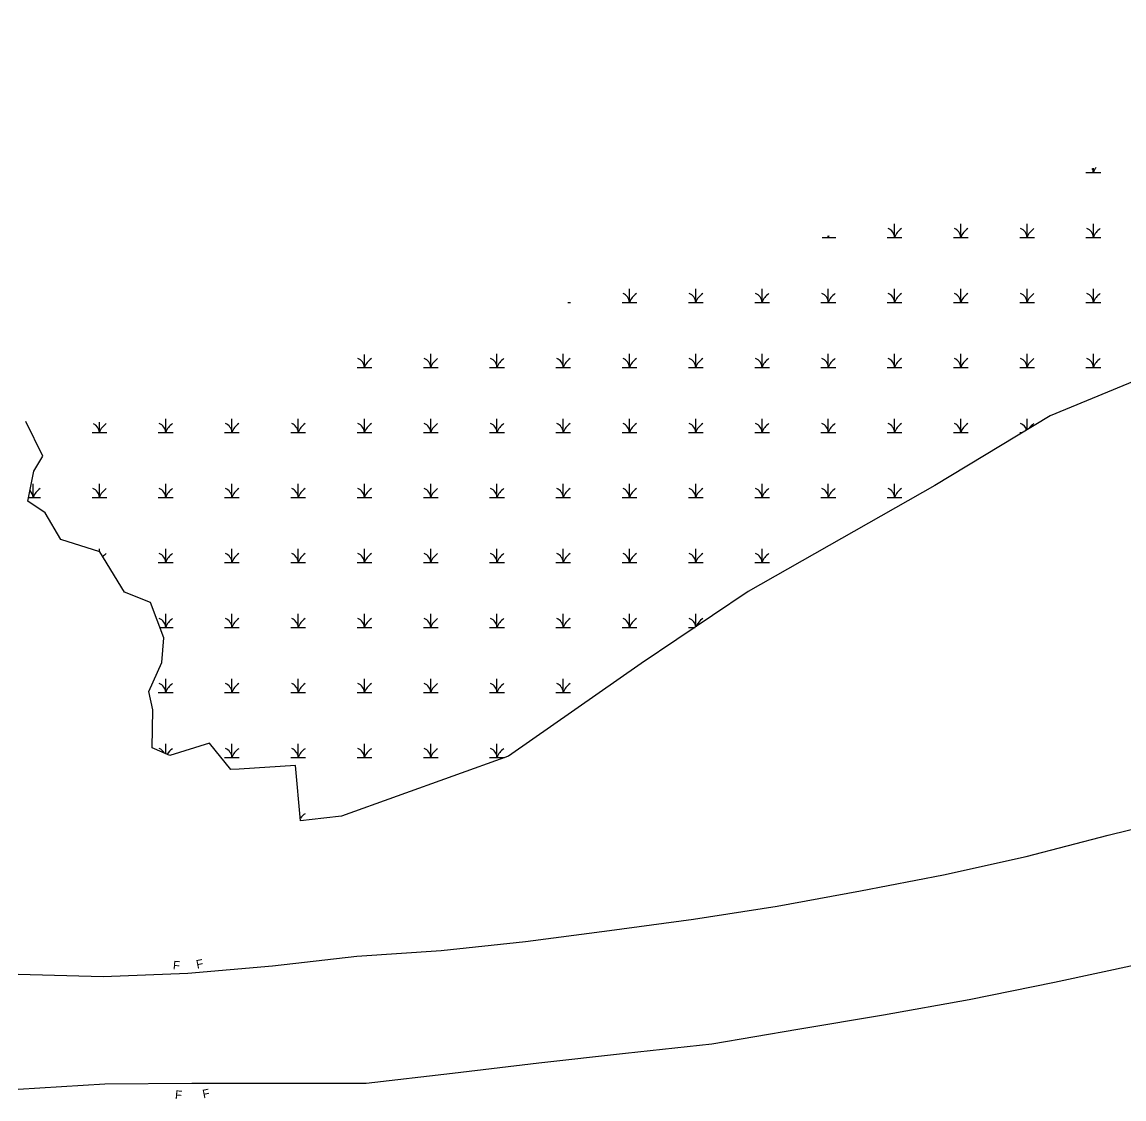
# Model space of a CAD drawing. Extents: x 2166958 to 2178986, y 64620 to 71122.
# Drawn here: x 2170969 to 2171611, y 65746 to 66374 of the extents above; entities that cross this region are included whole.
import ezdxf

# ---------------------------------------------------------------- set-up
doc = ezdxf.new("R2010")
doc.units = 0
for name, color, linetype in [('Default', 7, 'Continuous'), ('Prop Horizontal Alignment', 7, 'Continuous'), ('Prop Horizontal Alignment Station Label', 7, 'Continuous')]:
    doc.layers.add(name, color=color, linetype=linetype)

msp = doc.modelspace()

# ---------------------------------------------------------------- linework, layer by layer
at = {"layer": 'Default'}
for p, q in [((2171601.8, 65900.14), (2171649.69, 65911.92)), ((2171554.06, 65887.64), (2171601.8, 65900.14)), ((2171505.88, 65876.97), (2171554.06, 65887.64)), ((2171457.43, 65867.63), (2171505.88, 65876.97)), ((2171408.89, 65858.73), (2171457.43, 65867.63)), ((2171360.12, 65851.19), (2171408.89, 65858.73)), ((2171311.24, 65844.47), (2171360.12, 65851.19)), ((2171262.29, 65838.16), (2171311.24, 65844.47)), ((2171213.21, 65832.86), (2171262.29, 65838.16)), ((2171163.97, 65829.48), (2171213.21, 65832.86)), ((2171065.59, 65819.71), (2171114.86, 65823.94)), ((2171114.86, 65823.94), (2171163.97, 65829.48)), ((2171570.47, 65814.43), (2171620.11, 65824.97)), ((2170966.76, 65819.06), (2171016.19, 65817.74)), ((2171016.19, 65817.74), (2171065.59, 65819.71)), ((2171520.78, 65804.27), (2171570.47, 65814.43)), ((2171470.87, 65795.29), (2171520.78, 65804.27)), ((2171420.87, 65786.96), (2171470.87, 65795.29)), ((2171370.88, 65778.52), (2171420.87, 65786.96)), ((2171270.12, 65767.37), (2171320.48, 65773)), ((2171320.48, 65773), (2171370.88, 65778.52)), ((2171219.8, 65761.39), (2171270.12, 65767.37)), ((2171169.41, 65755.6), (2171219.8, 65761.39)), ((2170966.75, 65752.04), (2171017.34, 65755.19)), ((2171017.34, 65755.19), (2171067.95, 65755.43)), ((2171067.95, 65755.43), (2171118.63, 65755.49)), ((2171118.63, 65755.49), (2171169.41, 65755.6))]:
    msp.add_line(p, q, dxfattribs=at)
at = {"layer": 'Prop Horizontal Alignment'}
for points in [[(2171926.17, 66374.06), (2171888.59, 66346.6), (2171830.57, 66300.74), (2171772.74, 66253.86), (2171740.21, 66211.09), (2171680.33, 66190.92), (2171567.93, 66144.52), (2171500.72, 66103.8), (2171392.09, 66042.03), (2171329.77, 66000.07), (2171252.42, 65946.08), (2171155.09, 65911.07), (2171144.83, 65909.93)], [(2171144.83, 65909.93), (2171131.3, 65908.42), (2171128.42, 65940.58), (2171095.59, 65938.61), (2171090.61, 65938.31), (2171078.26, 65953.77), (2171055.21, 65946.44), (2171044.83, 65950.92), (2171045.23, 65973.08), (2171042.81, 65983.86), (2171050.36, 66000.7), (2171051.65, 66015.18), (2171043.78, 66035.64), (2171028.65, 66041.62), (2171014.36, 66065.19), (2170991.57, 66072.48), (2170982.57, 66087.94), (2170972.47, 66094.68), (2170975.83, 66112.25), (2170981.13, 66121), (2170971.28, 66141.23)]]:
    msp.add_lwpolyline(points, dxfattribs=at)
at = {"layer": 'Prop Horizontal Alignment Station Label'}
for p, q in [((2171588.82, 66286.39), (2171597.42, 66286.39)), ((2171593.12, 66286.39), (2171593.12, 66288.88)), ((2171477.32, 66248.5), (2171477.32, 66256.39)), ((2171515.92, 66248.5), (2171515.92, 66256.39)), ((2171554.52, 66248.5), (2171554.52, 66256.39)), ((2171593.12, 66248.5), (2171593.12, 66256.39)), ((2171435.21, 66248.5), (2171443.02, 66248.5)), ((2171438.72, 66248.5), (2171438.72, 66249.4)), ((2171473.02, 66248.5), (2171481.62, 66248.5)), ((2171511.62, 66248.5), (2171520.22, 66248.5)), ((2171550.22, 66248.5), (2171558.82, 66248.5)), ((2171588.82, 66248.5), (2171597.42, 66248.5)), ((2171322.91, 66210.61), (2171322.91, 66218.5)), ((2171361.51, 66210.61), (2171361.51, 66218.5)), ((2171400.12, 66210.61), (2171400.12, 66218.5)), ((2171438.72, 66210.61), (2171438.72, 66218.5)), ((2171477.32, 66210.61), (2171477.32, 66218.5)), ((2171515.92, 66210.61), (2171515.92, 66218.5)), ((2171554.52, 66210.61), (2171554.52, 66218.5)), ((2171593.12, 66210.61), (2171593.12, 66218.5)), ((2171287.05, 66210.61), (2171288.61, 66210.61)), ((2171318.61, 66210.61), (2171327.21, 66210.61)), ((2171357.21, 66210.61), (2171365.82, 66210.61)), ((2171395.82, 66210.61), (2171404.42, 66210.61)), ((2171434.42, 66210.61), (2171443.02, 66210.61)), ((2171473.02, 66210.61), (2171481.62, 66210.61)), ((2171511.62, 66210.61), (2171520.22, 66210.61)), ((2171550.22, 66210.61), (2171558.82, 66210.61)), ((2171588.82, 66210.61), (2171597.42, 66210.61)), ((2171168.51, 66172.72), (2171168.51, 66180.29)), ((2171207.11, 66172.72), (2171207.11, 66180.61)), ((2171245.71, 66172.72), (2171245.71, 66180.61)), ((2171284.31, 66172.72), (2171284.31, 66180.61)), ((2171322.91, 66172.72), (2171322.91, 66180.61)), ((2171361.51, 66172.72), (2171361.51, 66180.61)), ((2171400.12, 66172.72), (2171400.12, 66180.61)), ((2171438.72, 66172.72), (2171438.72, 66180.61)), ((2171477.32, 66172.72), (2171477.32, 66180.61)), ((2171515.92, 66172.72), (2171515.92, 66180.61)), ((2171554.52, 66172.72), (2171554.52, 66180.61)), ((2171593.12, 66172.72), (2171593.12, 66180.61)), ((2171164.21, 66172.72), (2171172.81, 66172.72)), ((2171202.81, 66172.72), (2171211.41, 66172.72)), ((2171241.41, 66172.72), (2171250.01, 66172.72)), ((2171280.01, 66172.72), (2171288.61, 66172.72)), ((2171318.61, 66172.72), (2171327.21, 66172.72)), ((2171357.21, 66172.72), (2171365.82, 66172.72)), ((2171395.82, 66172.72), (2171404.42, 66172.72)), ((2171434.42, 66172.72), (2171443.02, 66172.72)), ((2171473.02, 66172.72), (2171481.62, 66172.72)), ((2171511.62, 66172.72), (2171520.22, 66172.72)), ((2171550.22, 66172.72), (2171558.82, 66172.72)), ((2171588.82, 66172.72), (2171597.42, 66172.72)), ((2171014.1, 66134.83), (2171014.1, 66140.81)), ((2171052.7, 66134.83), (2171052.7, 66142.72)), ((2171091.3, 66134.83), (2171091.3, 66142.72)), ((2171129.91, 66134.83), (2171129.91, 66142.72)), ((2171168.51, 66134.83), (2171168.51, 66142.72)), ((2171207.11, 66134.83), (2171207.11, 66142.72)), ((2171245.71, 66134.83), (2171245.71, 66142.72)), ((2171284.31, 66134.83), (2171284.31, 66142.72)), ((2171322.91, 66134.83), (2171322.91, 66142.72)), ((2171361.51, 66134.83), (2171361.51, 66142.72)), ((2171400.12, 66134.83), (2171400.12, 66142.72)), ((2171438.72, 66134.83), (2171438.72, 66142.72)), ((2171477.32, 66134.83), (2171477.32, 66142.72)), ((2171515.92, 66134.83), (2171515.92, 66142.72)), ((2171554.52, 66136.4), (2171554.52, 66142.72)), ((2171009.8, 66134.83), (2171018.4, 66134.83)), ((2171048.4, 66134.83), (2171057, 66134.83)), ((2171087, 66134.83), (2171095.6, 66134.83)), ((2171125.6, 66134.83), (2171134.21, 66134.83)), ((2171164.21, 66134.83), (2171172.81, 66134.83)), ((2171202.81, 66134.83), (2171211.41, 66134.83)), ((2171241.41, 66134.83), (2171250.01, 66134.83)), ((2171280.01, 66134.83), (2171288.61, 66134.83)), ((2171318.61, 66134.83), (2171327.21, 66134.83)), ((2171357.21, 66134.83), (2171365.82, 66134.83)), ((2171395.82, 66134.83), (2171404.42, 66134.83)), ((2171434.42, 66134.83), (2171443.02, 66134.83)), ((2171473.02, 66134.83), (2171481.62, 66134.83)), ((2171511.62, 66134.83), (2171520.22, 66134.83)), ((2171550.22, 66134.83), (2171551.93, 66134.83)), ((2170975.5, 66096.94), (2170975.5, 66104.83)), ((2171014.1, 66096.94), (2171014.1, 66104.83)), ((2171052.7, 66096.94), (2171052.7, 66104.83)), ((2171091.3, 66096.94), (2171091.3, 66104.83)), ((2171129.91, 66096.94), (2171129.91, 66104.83)), ((2171168.51, 66096.94), (2171168.51, 66104.83)), ((2171207.11, 66096.94), (2171207.11, 66104.83)), ((2171245.71, 66096.94), (2171245.71, 66104.83)), ((2171284.31, 66096.94), (2171284.31, 66104.83)), ((2171322.91, 66096.94), (2171322.91, 66104.83)), ((2171361.51, 66096.94), (2171361.51, 66104.83)), ((2171400.12, 66096.94), (2171400.12, 66104.83)), ((2171438.72, 66096.94), (2171438.72, 66104.83)), ((2171477.32, 66096.94), (2171477.32, 66104.83)), ((2170972.91, 66096.94), (2170979.8, 66096.94)), ((2171009.8, 66096.94), (2171018.4, 66096.94)), ((2171048.4, 66096.94), (2171057, 66096.94)), ((2171087, 66096.94), (2171095.6, 66096.94)), ((2171125.6, 66096.94), (2171134.21, 66096.94)), ((2171164.21, 66096.94), (2171172.81, 66096.94)), ((2171202.81, 66096.94), (2171211.41, 66096.94)), ((2171241.41, 66096.94), (2171250.01, 66096.94)), ((2171280.01, 66096.94), (2171288.61, 66096.94)), ((2171318.61, 66096.94), (2171327.21, 66096.94)), ((2171357.21, 66096.94), (2171365.82, 66096.94)), ((2171395.82, 66096.94), (2171404.42, 66096.94)), ((2171434.42, 66096.94), (2171443.02, 66096.94)), ((2171473.02, 66096.94), (2171481.62, 66096.94)), ((2171014.1, 66065.27), (2171014.1, 66066.94)), ((2171052.7, 66059.05), (2171052.7, 66066.94)), ((2171091.3, 66059.05), (2171091.3, 66066.94)), ((2171129.91, 66059.05), (2171129.91, 66066.94)), ((2171168.51, 66059.05), (2171168.51, 66066.94)), ((2171207.11, 66059.05), (2171207.11, 66066.94)), ((2171245.71, 66059.05), (2171245.71, 66066.94)), ((2171284.31, 66059.05), (2171284.31, 66066.94)), ((2171322.91, 66059.05), (2171322.91, 66066.94)), ((2171361.51, 66059.05), (2171361.51, 66066.94)), ((2171400.12, 66059.05), (2171400.12, 66066.94)), ((2171018.09, 66059.05), (2171018.4, 66059.05)), ((2171048.4, 66059.05), (2171057, 66059.05)), ((2171087, 66059.05), (2171095.6, 66059.05)), ((2171125.6, 66059.05), (2171134.21, 66059.05)), ((2171164.21, 66059.05), (2171172.81, 66059.05)), ((2171202.81, 66059.05), (2171211.41, 66059.05)), ((2171241.41, 66059.05), (2171250.01, 66059.05)), ((2171280.01, 66059.05), (2171288.61, 66059.05)), ((2171318.61, 66059.05), (2171327.21, 66059.05)), ((2171357.21, 66059.05), (2171365.82, 66059.05)), ((2171395.82, 66059.05), (2171404.42, 66059.05)), ((2171052.7, 66021.16), (2171052.7, 66029.05)), ((2171091.3, 66021.16), (2171091.3, 66029.05)), ((2171129.91, 66021.16), (2171129.91, 66029.05)), ((2171168.51, 66021.16), (2171168.51, 66029.05)), ((2171207.11, 66021.16), (2171207.11, 66029.05)), ((2171245.71, 66021.16), (2171245.71, 66029.05)), ((2171284.31, 66021.16), (2171284.31, 66029.05)), ((2171322.91, 66021.16), (2171322.91, 66029.05)), ((2171361.51, 66021.44), (2171361.51, 66029.05)), ((2171049.35, 66021.16), (2171057, 66021.16)), ((2171087, 66021.16), (2171095.6, 66021.16)), ((2171125.6, 66021.16), (2171134.21, 66021.16)), ((2171164.21, 66021.16), (2171172.81, 66021.16)), ((2171202.81, 66021.16), (2171211.41, 66021.16)), ((2171241.41, 66021.16), (2171250.01, 66021.16)), ((2171280.01, 66021.16), (2171288.61, 66021.16)), ((2171318.61, 66021.16), (2171327.21, 66021.16)), ((2171357.21, 66021.16), (2171361.09, 66021.16)), ((2171052.7, 65983.27), (2171052.7, 65991.16)), ((2171091.3, 65983.27), (2171091.3, 65991.16)), ((2171129.91, 65983.27), (2171129.91, 65991.16)), ((2171168.51, 65983.27), (2171168.51, 65991.16)), ((2171207.11, 65983.27), (2171207.11, 65991.16)), ((2171245.71, 65983.27), (2171245.71, 65991.16)), ((2171284.31, 65983.27), (2171284.31, 65991.16)), ((2171048.4, 65983.27), (2171057, 65983.27)), ((2171087, 65983.27), (2171095.6, 65983.27)), ((2171125.6, 65983.27), (2171134.21, 65983.27)), ((2171164.21, 65983.27), (2171172.81, 65983.27)), ((2171202.81, 65983.27), (2171211.41, 65983.27)), ((2171241.41, 65983.27), (2171250.01, 65983.27)), ((2171280.01, 65983.27), (2171288.61, 65983.27)), ((2171052.7, 65947.52), (2171052.7, 65953.27)), ((2171091.3, 65945.38), (2171091.3, 65953.27)), ((2171129.91, 65945.38), (2171129.91, 65953.27)), ((2171168.51, 65945.38), (2171168.51, 65953.27)), ((2171207.11, 65945.38), (2171207.11, 65953.27)), ((2171245.71, 65945.38), (2171245.71, 65953.27)), ((2171087, 65945.38), (2171095.6, 65945.38)), ((2171125.6, 65945.38), (2171134.21, 65945.38)), ((2171164.21, 65945.38), (2171172.81, 65945.38)), ((2171202.81, 65945.38), (2171211.41, 65945.38)), ((2171241.41, 65945.38), (2171250.01, 65945.38))]:
    msp.add_line(p, q, dxfattribs=at)
for centre, radius, start, end in [((2171586.99, 66285.95), 6.15, 4.14034, 26.79507), ((2171602.24, 66283.36), 9.61, 141.98586, 161.62219), ((2171432.58, 66248.06), 6.15, 4.14034, 12.28321), ((2171447.84, 66245.47), 9.61, 155.22805, 161.62219), ((2171471.19, 66248.06), 6.15, 4.14034, 67.53497), ((2171486.44, 66245.47), 9.61, 122.12745, 161.62219), ((2171509.79, 66248.06), 6.15, 4.14034, 67.53497), ((2171525.04, 66245.47), 9.61, 122.12745, 161.62219), ((2171548.39, 66248.06), 6.15, 4.14034, 67.53497), ((2171563.64, 66245.47), 9.61, 122.12745, 161.62219), ((2171586.99, 66248.06), 6.15, 4.14034, 67.53497), ((2171602.24, 66245.47), 9.61, 122.12745, 161.62219), ((2171316.78, 66210.17), 6.15, 4.14034, 67.53497), ((2171332.03, 66207.58), 9.61, 122.12745, 161.62219), ((2171355.38, 66210.17), 6.15, 4.14034, 67.53497), ((2171370.64, 66207.58), 9.61, 122.12745, 161.62219), ((2171393.98, 66210.17), 6.15, 4.14034, 67.53497), ((2171409.24, 66207.58), 9.61, 122.12745, 161.62219), ((2171432.58, 66210.17), 6.15, 4.14034, 67.53497), ((2171447.84, 66207.58), 9.61, 122.12745, 161.62219), ((2171471.19, 66210.17), 6.15, 4.14034, 67.53497), ((2171486.44, 66207.58), 9.61, 122.12745, 161.62219), ((2171509.79, 66210.17), 6.15, 4.14034, 67.53497), ((2171525.04, 66207.58), 9.61, 122.12745, 161.62219), ((2171548.39, 66210.17), 6.15, 4.14034, 67.53497), ((2171563.64, 66207.58), 9.61, 122.12745, 161.62219), ((2171586.99, 66210.17), 6.15, 4.14034, 67.53497), ((2171602.24, 66207.58), 9.61, 122.12745, 161.62219), ((2171162.37, 66172.28), 6.15, 4.14034, 67.53497), ((2171177.63, 66169.69), 9.61, 122.12745, 161.62219), ((2171200.98, 66172.28), 6.15, 4.14034, 67.53497), ((2171216.23, 66169.69), 9.61, 122.12745, 161.62219), ((2171239.58, 66172.28), 6.15, 4.14034, 67.53497), ((2171254.83, 66169.69), 9.61, 122.12745, 161.62219), ((2171278.18, 66172.28), 6.15, 4.14034, 67.53497), ((2171293.43, 66169.69), 9.61, 122.12745, 161.62219), ((2171316.78, 66172.28), 6.15, 4.14034, 67.53497), ((2171332.03, 66169.69), 9.61, 122.12745, 161.62219), ((2171355.38, 66172.28), 6.15, 4.14034, 67.53497), ((2171370.64, 66169.69), 9.61, 122.12745, 161.62219), ((2171393.98, 66172.28), 6.15, 4.14034, 67.53497), ((2171409.24, 66169.69), 9.61, 122.12745, 161.62219), ((2171432.58, 66172.28), 6.15, 4.14034, 67.53497), ((2171447.84, 66169.69), 9.61, 122.12745, 161.62219), ((2171471.19, 66172.28), 6.15, 4.14034, 67.53497), ((2171486.44, 66169.69), 9.61, 122.12745, 161.62219), ((2171509.79, 66172.28), 6.15, 4.14034, 67.53497), ((2171525.04, 66169.69), 9.61, 122.12745, 161.62219), ((2171548.39, 66172.28), 6.15, 4.14034, 67.53497), ((2171563.64, 66169.69), 9.61, 122.12745, 161.62219), ((2171586.99, 66172.28), 6.15, 4.14034, 67.53497), ((2171602.24, 66169.69), 9.61, 122.12745, 161.62219), ((2171007.97, 66134.39), 6.15, 4.14034, 64.22013), ((2171023.22, 66131.8), 9.61, 122.12745, 161.62219), ((2171046.57, 66134.39), 6.15, 4.14034, 67.53497), ((2171061.82, 66131.8), 9.61, 122.12745, 161.62219), ((2171085.17, 66134.39), 6.15, 4.14034, 67.53497), ((2171100.42, 66131.8), 9.61, 122.12745, 161.62219), ((2171123.77, 66134.39), 6.15, 4.14034, 67.53497), ((2171139.03, 66131.8), 9.61, 122.12745, 161.62219), ((2171162.37, 66134.39), 6.15, 4.14034, 67.53497), ((2171177.63, 66131.8), 9.61, 122.12745, 161.62219), ((2171200.98, 66134.39), 6.15, 4.14034, 67.53497), ((2171216.23, 66131.8), 9.61, 122.12745, 161.62219), ((2171239.58, 66134.39), 6.15, 4.14034, 67.53497), ((2171254.83, 66131.8), 9.61, 122.12745, 161.62219), ((2171278.18, 66134.39), 6.15, 4.14034, 67.53497), ((2171293.43, 66131.8), 9.61, 122.12745, 161.62219), ((2171316.78, 66134.39), 6.15, 4.14034, 67.53497), ((2171332.03, 66131.8), 9.61, 122.12745, 161.62219), ((2171355.38, 66134.39), 6.15, 4.14034, 67.53497), ((2171370.64, 66131.8), 9.61, 122.12745, 161.62219), ((2171393.98, 66134.39), 6.15, 4.14034, 67.53497), ((2171409.24, 66131.8), 9.61, 122.12745, 161.62219), ((2171432.58, 66134.39), 6.15, 4.14034, 67.53497), ((2171447.84, 66131.8), 9.61, 122.12745, 161.62219), ((2171471.19, 66134.39), 6.15, 4.14034, 67.53497), ((2171486.44, 66131.8), 9.61, 122.12745, 161.62219), ((2171509.79, 66134.39), 6.15, 4.14034, 67.53497), ((2171525.04, 66131.8), 9.61, 122.12745, 161.62219), ((2171548.39, 66134.39), 6.15, 17.52513, 67.53497), ((2171563.64, 66131.8), 9.61, 122.12745, 146.89571), ((2170969.37, 66096.49), 6.15, 4.14034, 45.68044), ((2170984.62, 66093.91), 9.61, 122.12745, 161.62219), ((2171007.97, 66096.49), 6.15, 4.14034, 67.53497), ((2171023.22, 66093.91), 9.61, 122.12745, 161.62219), ((2171046.57, 66096.49), 6.15, 4.14034, 67.53497), ((2171061.82, 66093.91), 9.61, 122.12745, 161.62219), ((2171085.17, 66096.49), 6.15, 4.14034, 67.53497), ((2171100.42, 66093.91), 9.61, 122.12745, 161.62219), ((2171123.77, 66096.49), 6.15, 4.14034, 67.53497), ((2171139.03, 66093.91), 9.61, 122.12745, 161.62219), ((2171162.37, 66096.49), 6.15, 4.14034, 67.53497), ((2171177.63, 66093.91), 9.61, 122.12745, 161.62219), ((2171200.98, 66096.49), 6.15, 4.14034, 67.53497), ((2171216.23, 66093.91), 9.61, 122.12745, 161.62219), ((2171239.58, 66096.49), 6.15, 4.14034, 67.53497), ((2171254.83, 66093.91), 9.61, 122.12745, 161.62219), ((2171278.18, 66096.49), 6.15, 4.14034, 67.53497), ((2171293.43, 66093.91), 9.61, 122.12745, 161.62219), ((2171316.78, 66096.49), 6.15, 4.14034, 67.53497), ((2171332.03, 66093.91), 9.61, 122.12745, 161.62219), ((2171355.38, 66096.49), 6.15, 4.14034, 67.53497), ((2171370.64, 66093.91), 9.61, 122.12745, 161.62219), ((2171393.98, 66096.49), 6.15, 4.14034, 67.53497), ((2171409.24, 66093.91), 9.61, 122.12745, 161.62219), ((2171432.58, 66096.49), 6.15, 4.14034, 67.53497), ((2171447.84, 66093.91), 9.61, 122.12745, 161.62219), ((2171471.19, 66096.49), 6.15, 4.14034, 67.53497), ((2171486.44, 66093.91), 9.61, 122.12745, 161.62219), ((2171023.22, 66056.02), 9.61, 122.12745, 138.28827), ((2171046.57, 66058.6), 6.15, 4.14034, 67.53497), ((2171061.82, 66056.02), 9.61, 122.12745, 161.62219), ((2171085.17, 66058.6), 6.15, 4.14034, 67.53497), ((2171100.42, 66056.02), 9.61, 122.12745, 161.62219), ((2171123.77, 66058.6), 6.15, 4.14034, 67.53497), ((2171139.03, 66056.02), 9.61, 122.12745, 161.62219), ((2171162.37, 66058.6), 6.15, 4.14034, 67.53497), ((2171177.63, 66056.02), 9.61, 122.12745, 161.62219), ((2171200.98, 66058.6), 6.15, 4.14034, 67.53497), ((2171216.23, 66056.02), 9.61, 122.12745, 161.62219), ((2171239.58, 66058.6), 6.15, 4.14034, 67.53497), ((2171254.83, 66056.02), 9.61, 122.12745, 161.62219), ((2171278.18, 66058.6), 6.15, 4.14034, 67.53497), ((2171293.43, 66056.02), 9.61, 122.12745, 161.62219), ((2171316.78, 66058.6), 6.15, 4.14034, 67.53497), ((2171332.03, 66056.02), 9.61, 122.12745, 161.62219), ((2171355.38, 66058.6), 6.15, 4.14034, 67.53497), ((2171370.64, 66056.02), 9.61, 122.12745, 161.62219), ((2171393.98, 66058.6), 6.15, 4.14034, 67.53497), ((2171409.24, 66056.02), 9.61, 122.12745, 161.62219), ((2171046.57, 66020.71), 6.15, 4.14034, 67.53497), ((2171061.82, 66018.13), 9.61, 122.12745, 161.62219), ((2171085.17, 66020.71), 6.15, 4.14034, 67.53497), ((2171100.42, 66018.13), 9.61, 122.12745, 161.62219), ((2171123.77, 66020.71), 6.15, 4.14034, 67.53497), ((2171139.03, 66018.13), 9.61, 122.12745, 161.62219), ((2171162.37, 66020.71), 6.15, 4.14034, 67.53497), ((2171177.63, 66018.13), 9.61, 122.12745, 161.62219), ((2171200.98, 66020.71), 6.15, 4.14034, 67.53497), ((2171216.23, 66018.13), 9.61, 122.12745, 161.62219), ((2171239.58, 66020.71), 6.15, 4.14034, 67.53497), ((2171254.83, 66018.13), 9.61, 122.12745, 161.62219), ((2171278.18, 66020.71), 6.15, 4.14034, 67.53497), ((2171293.43, 66018.13), 9.61, 122.12745, 161.62219), ((2171316.78, 66020.71), 6.15, 4.14034, 67.53497), ((2171332.03, 66018.13), 9.61, 122.12745, 161.62219), ((2171355.38, 66020.71), 6.15, 6.63347, 67.53497), ((2171370.64, 66018.13), 9.61, 122.12745, 159.26661), ((2171046.57, 65982.82), 6.15, 4.14034, 67.53497), ((2171061.82, 65980.24), 9.61, 122.12745, 161.62219), ((2171085.17, 65982.82), 6.15, 4.14034, 67.53497), ((2171100.42, 65980.24), 9.61, 122.12745, 161.62219), ((2171123.77, 65982.82), 6.15, 4.14034, 67.53497), ((2171139.03, 65980.24), 9.61, 122.12745, 161.62219), ((2171162.37, 65982.82), 6.15, 4.14034, 67.53497), ((2171177.63, 65980.24), 9.61, 122.12745, 161.62219), ((2171200.98, 65982.82), 6.15, 4.14034, 67.53497), ((2171216.23, 65980.24), 9.61, 122.12745, 161.62219), ((2171239.58, 65982.82), 6.15, 4.14034, 67.53497), ((2171254.83, 65980.24), 9.61, 122.12745, 161.62219), ((2171278.18, 65982.82), 6.15, 4.14034, 67.53497), ((2171293.43, 65980.24), 9.61, 122.12745, 161.62219), ((2171046.57, 65944.93), 6.15, 28.0843, 67.53497), ((2171061.82, 65942.35), 9.61, 122.12745, 149.85937), ((2171085.17, 65944.93), 6.15, 4.14034, 67.53497), ((2171100.42, 65942.35), 9.61, 122.12745, 161.62219), ((2171123.77, 65944.93), 6.15, 4.14034, 67.53497), ((2171139.03, 65942.35), 9.61, 122.12745, 161.62219), ((2171162.37, 65944.93), 6.15, 4.14034, 67.53497), ((2171177.63, 65942.35), 9.61, 122.12745, 161.62219), ((2171200.98, 65944.93), 6.15, 4.14034, 67.53497), ((2171216.23, 65942.35), 9.61, 122.12745, 161.62219), ((2171239.58, 65944.93), 6.15, 4.14034, 67.53497), ((2171254.83, 65942.35), 9.61, 122.12745, 161.62219), ((2171139.03, 65904.46), 9.61, 122.12745, 144.90844)]:
    msp.add_arc(centre, radius, start, end, dxfattribs=at)

# ---------------------------------------------------------------- texts
at = {"layer": 'Default'}
for rotation, p in [(355.32023, (2171056.77, 65821.89)), (11.58631, (2171071.02, 65822.18)), (355.32023, (2171057.98, 65746.39)), (11.58631, (2171074.71, 65746.6))]:
    msp.add_text('F', height=5, rotation=rotation, dxfattribs=at).set_placement(p)

doc.saveas('drawing.dxf')
